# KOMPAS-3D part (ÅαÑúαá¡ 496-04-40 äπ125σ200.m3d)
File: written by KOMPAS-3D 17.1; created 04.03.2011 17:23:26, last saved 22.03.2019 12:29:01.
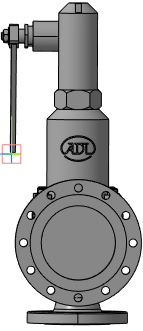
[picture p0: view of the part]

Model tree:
1. Плоскость XY
2. Плоскость ZX
3. Плоскость ZY
4. Ось X
5. Ось Y
6. Ось Z
7. Начало координат
8. Операция без истории:2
